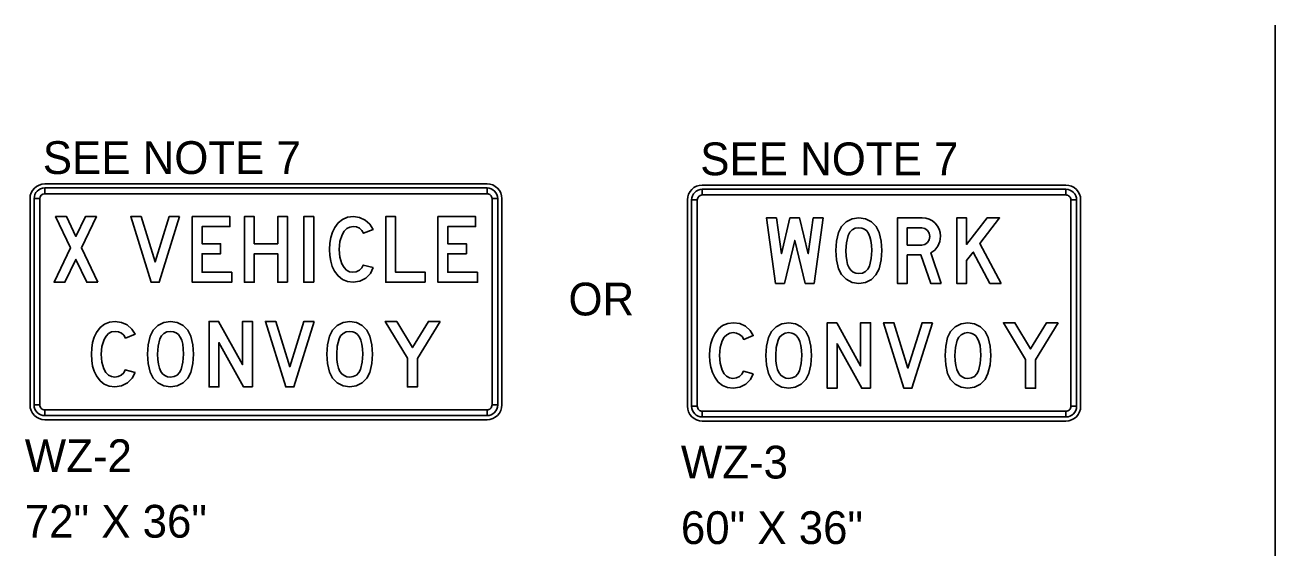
# Model space of a CAD drawing. Extents: x -747 to 834, y -5485 to -3577.
# Drawn here: x 87.7 to 316.6, y -4538 to -4442.2 of the extents above; entities that cross this region are included whole.
import ezdxf

# ---------------------------------------------------------------- set-up
doc = ezdxf.new("R2010")
doc.units = 0
doc.layers.add('Working Level 1', color=7, linetype='Continuous')

msp = doc.modelspace()

# ---------------------------------------------------------------- linework, layer by layer
at = {"layer": 'Working Level 1'}
for p, q in [((316.57, -4442.19), (316.57, -5484.51)), ((172.28, -4471.28), (91.28, -4471.28)), ((91.28, -4473.08), (91.28, -4472.03)), ((172.28, -4472.03), (172.28, -4473.08)), ((278.28, -4471.51), (211.68, -4471.51)), ((211.68, -4473.31), (211.68, -4472.26)), ((278.28, -4472.26), (278.28, -4473.31)), ((88.58, -4473.98), (88.58, -4511.77)), ((89.33, -4473.98), (90.38, -4473.98)), ((173.18, -4473.98), (174.23, -4473.98)), ((174.98, -4511.77), (174.98, -4473.98)), ((208.98, -4474.21), (208.98, -4512.01)), ((209.73, -4474.21), (210.78, -4474.21)), ((279.18, -4474.21), (280.23, -4474.21)), ((280.98, -4512.01), (280.98, -4474.21)), ((90.38, -4511.77), (89.33, -4511.77)), ((174.23, -4511.77), (173.18, -4511.77)), ((91.28, -4513.72), (91.28, -4512.67)), ((172.28, -4512.67), (172.28, -4513.72)), ((210.78, -4512.01), (209.73, -4512.01)), ((211.68, -4513.96), (211.68, -4512.91)), ((278.28, -4512.91), (278.28, -4513.96)), ((280.23, -4512.01), (279.18, -4512.01)), ((91.28, -4514.47), (172.28, -4514.47)), ((211.68, -4514.71), (278.28, -4514.71))]:
    msp.add_line(p, q, dxfattribs=at)
for points in [[(172.28, -4472.03), (91.28, -4472.03), (91.28, -4473.08), (172.28, -4473.08), (172.28, -4472.03)], [(278.28, -4472.26), (211.68, -4472.26), (211.68, -4473.31), (278.28, -4473.31), (278.28, -4472.26)], [(89.33, -4473.98), (89.33, -4511.77), (90.38, -4511.77), (90.38, -4473.98), (89.33, -4473.98)], [(174.23, -4511.77), (174.23, -4473.98), (173.18, -4473.98), (173.18, -4511.77), (174.23, -4511.77)], [(209.73, -4474.21), (209.73, -4512.01), (210.78, -4512.01), (210.78, -4474.21), (209.73, -4474.21)], [(280.23, -4512.01), (280.23, -4474.21), (279.18, -4474.21), (279.18, -4512.01), (280.23, -4512.01)], [(100.98, -4489.28), (97.99, -4482.99), (100.73, -4477.28), (98.72, -4477.28), (96.98, -4480.9), (95.26, -4477.28), (93.25, -4477.28), (95.98, -4483), (92.97, -4489.28), (94.97, -4489.28), (96.98, -4485.1), (98.97, -4489.28)], [(115.96, -4477.28), (114.07, -4477.28), (111.49, -4485.57), (108.92, -4477.28), (107.03, -4477.28), (110.75, -4489.28), (112.24, -4489.28)], [(125.53, -4487.46), (120.09, -4487.46), (120.09, -4484.07), (123.49, -4484.07), (123.49, -4482.26), (120.09, -4482.26), (120.09, -4479.09), (125.17, -4479.09), (125.17, -4477.28), (118.28, -4477.28), (118.28, -4489.28), (125.53, -4489.28)], [(135.76, -4489.28), (135.76, -4477.28), (133.95, -4477.28), (133.95, -4482.26), (129.65, -4482.26), (129.65, -4477.28), (127.84, -4477.28), (127.84, -4489.28), (129.65, -4489.28), (129.65, -4484.07), (133.95, -4484.07), (133.95, -4489.28)], [(140.53, -4489.28), (140.53, -4477.28), (138.72, -4477.28), (138.72, -4489.28)], [(151.41, -4486.61), (149.6, -4486.15), (149.33, -4486.68), (148.89, -4487.1), (148.33, -4487.37), (147.7, -4487.46), (147.07, -4487.37), (146.53, -4487.08), (146.08, -4486.6), (145.71, -4485.94), (145.34, -4484.7), (145.22, -4483.28), (145.34, -4481.84), (145.72, -4480.6), (146.1, -4479.94), (146.57, -4479.47), (147.12, -4479.18), (147.76, -4479.09), (148.36, -4479.17), (148.91, -4479.42), (149.36, -4479.81), (149.67, -4480.31), (151.41, -4479.63), (150.83, -4478.67), (149.97, -4477.92), (148.93, -4477.44), (147.79, -4477.28), (146.73, -4477.4), (145.81, -4477.78), (145.03, -4478.4), (144.37, -4479.28), (143.95, -4480.14), (143.65, -4481.1), (143.47, -4482.14), (143.41, -4483.27), (143.46, -4484.4), (143.64, -4485.44), (143.94, -4486.39), (144.36, -4487.25), (145, -4488.14), (145.78, -4488.77), (146.69, -4489.15), (147.73, -4489.28), (148.95, -4489.09), (150.05, -4488.54), (150.9, -4487.68)], [(160.97, -4489.28), (160.97, -4487.46), (155.53, -4487.46), (155.53, -4477.28), (153.72, -4477.28), (153.72, -4489.28)], [(170.53, -4487.46), (165.09, -4487.46), (165.09, -4484.07), (168.49, -4484.07), (168.49, -4482.26), (165.09, -4482.26), (165.09, -4479.09), (170.17, -4479.09), (170.17, -4477.28), (163.28, -4477.28), (163.28, -4489.28), (170.53, -4489.28)], [(233.84, -4477.51), (232.01, -4477.51), (231.09, -4484.08), (229.51, -4477.51), (227.75, -4477.51), (226.17, -4484.09), (225.25, -4477.51), (223.42, -4477.51), (225.1, -4489.51), (226.73, -4489.51), (228.63, -4481.62), (230.53, -4489.51), (232.16, -4489.51)], [(244.54, -4483.5), (244.42, -4481.79), (244.06, -4480.19), (243.52, -4479.11), (242.66, -4478.25), (241.57, -4477.7), (240.35, -4477.51), (239.13, -4477.7), (238.05, -4478.25), (237.19, -4479.11), (236.66, -4480.2), (236.29, -4481.8), (236.17, -4483.5), (236.29, -4485.2), (236.66, -4486.81), (237.19, -4487.9), (238.05, -4488.76), (239.13, -4489.32), (240.35, -4489.51), (241.57, -4489.33), (242.65, -4488.77), (243.5, -4487.92), (244.05, -4486.83), (244.42, -4485.22)], [(242.73, -4483.51), (242.63, -4484.97), (242.31, -4486.32), (242.02, -4486.89), (241.57, -4487.33), (241, -4487.61), (240.36, -4487.7), (239.8, -4487.64), (239.32, -4487.44), (238.91, -4487.11), (238.57, -4486.65), (238.31, -4486.06), (238.13, -4485.34), (238.01, -4484.49), (237.98, -4483.51), (238.08, -4482.06), (238.4, -4480.71), (238.69, -4480.14), (239.14, -4479.7), (239.71, -4479.42), (240.36, -4479.32), (240.92, -4479.39), (241.4, -4479.58), (241.8, -4479.91), (242.14, -4480.37), (242.4, -4480.96), (242.58, -4481.68), (242.69, -4482.53)], [(255.43, -4489.51), (253.53, -4483.91), (254.27, -4483.39), (254.85, -4482.66), (255.22, -4481.81), (255.34, -4480.88), (255.28, -4480.21), (255.09, -4479.59), (254.78, -4479.02), (254.34, -4478.5), (253.82, -4478.07), (253.24, -4477.76), (252.62, -4477.57), (251.95, -4477.51), (247.42, -4477.51), (247.42, -4489.51), (249.23, -4489.51), (249.23, -4484.3), (251.74, -4484.3), (253.52, -4489.51)], [(249.23, -4482.49), (249.23, -4479.32), (251.87, -4479.32), (252.44, -4479.44), (252.93, -4479.79), (253.26, -4480.3), (253.37, -4480.91), (253.26, -4481.52), (252.93, -4482.03), (252.44, -4482.38), (251.87, -4482.49)], [(266.42, -4489.51), (262.52, -4482.2), (266.13, -4477.51), (263.85, -4477.51), (260.1, -4482.37), (260.1, -4477.51), (258.29, -4477.51), (258.29, -4489.51), (260.1, -4489.51), (260.1, -4485.34), (261.31, -4483.78), (264.37, -4489.51)], [(107.82, -4505.81), (106, -4505.35), (105.74, -4505.88), (105.3, -4506.3), (104.73, -4506.57), (104.11, -4506.66), (103.48, -4506.57), (102.94, -4506.28), (102.48, -4505.8), (102.11, -4505.14), (101.74, -4503.9), (101.62, -4502.48), (101.75, -4501.04), (102.13, -4499.8), (102.51, -4499.14), (102.97, -4498.67), (103.52, -4498.38), (104.17, -4498.29), (104.77, -4498.37), (105.31, -4498.62), (105.77, -4499.01), (106.08, -4499.51), (107.82, -4498.83), (107.23, -4497.87), (106.38, -4497.12), (105.34, -4496.64), (104.2, -4496.48), (103.14, -4496.6), (102.22, -4496.98), (101.43, -4497.6), (100.78, -4498.48), (100.35, -4499.34), (100.05, -4500.3), (99.87, -4501.34), (99.81, -4502.47), (99.87, -4503.6), (100.05, -4504.64), (100.34, -4505.59), (100.77, -4506.45), (101.41, -4507.34), (102.18, -4507.97), (103.09, -4508.35), (104.14, -4508.47), (105.36, -4508.29), (106.45, -4507.74), (107.31, -4506.88)], [(118.5, -4502.47), (118.38, -4500.76), (118.01, -4499.15), (117.47, -4498.07), (116.61, -4497.21), (115.52, -4496.66), (114.3, -4496.48), (113.08, -4496.66), (112, -4497.21), (111.15, -4498.07), (110.61, -4499.16), (110.24, -4500.77), (110.12, -4502.47), (110.24, -4504.17), (110.61, -4505.78), (111.15, -4506.87), (112, -4507.73), (113.08, -4508.29), (114.3, -4508.47), (115.52, -4508.29), (116.6, -4507.74), (117.46, -4506.88), (118, -4505.8), (118.37, -4504.19)], [(129.3, -4508.47), (129.3, -4496.48), (127.49, -4496.48), (127.49, -4504.36), (123.11, -4496.48), (121.37, -4496.48), (121.37, -4508.47), (123.18, -4508.47), (123.18, -4500.33), (127.7, -4508.47)], [(140.62, -4496.48), (138.73, -4496.48), (136.15, -4504.77), (133.58, -4496.48), (131.69, -4496.48), (135.4, -4508.47), (136.89, -4508.47)], [(151.31, -4502.47), (151.19, -4500.76), (150.82, -4499.15), (150.28, -4498.07), (149.42, -4497.21), (148.34, -4496.66), (147.12, -4496.48), (145.9, -4496.66), (144.82, -4497.21), (143.96, -4498.07), (143.42, -4499.16), (143.06, -4500.77), (142.94, -4502.47), (143.06, -4504.17), (143.42, -4505.78), (143.96, -4506.87), (144.82, -4507.73), (145.9, -4508.29), (147.12, -4508.47), (148.33, -4508.29), (149.42, -4507.74), (150.27, -4506.88), (150.81, -4505.8), (151.18, -4504.19)], [(163.68, -4496.48), (161.55, -4496.48), (158.61, -4501.27), (155.73, -4496.48), (153.62, -4496.48), (157.7, -4503.22), (157.7, -4508.47), (159.51, -4508.47), (159.51, -4503.27)], [(221.02, -4506.05), (219.21, -4505.59), (218.94, -4506.11), (218.5, -4506.53), (217.94, -4506.81), (217.31, -4506.9), (216.68, -4506.8), (216.14, -4506.52), (215.68, -4506.04), (215.31, -4505.37), (214.94, -4504.14), (214.82, -4502.71), (214.95, -4501.27), (215.33, -4500.04), (215.71, -4499.38), (216.17, -4498.9), (216.73, -4498.62), (217.37, -4498.52), (217.97, -4498.61), (218.52, -4498.85), (218.97, -4499.25), (219.28, -4499.75), (221.02, -4499.07), (220.43, -4498.1), (219.58, -4497.35), (218.54, -4496.87), (217.4, -4496.71), (216.34, -4496.84), (215.42, -4497.21), (214.63, -4497.84), (213.98, -4498.71), (213.55, -4499.58), (213.25, -4500.53), (213.07, -4501.57), (213.01, -4502.7), (213.07, -4503.83), (213.25, -4504.87), (213.55, -4505.82), (213.97, -4506.69), (214.61, -4507.57), (215.39, -4508.2), (216.29, -4508.59), (217.34, -4508.71), (218.56, -4508.53), (219.65, -4507.97), (220.51, -4507.12)], [(231.7, -4502.7), (231.58, -4500.99), (231.21, -4499.39), (230.67, -4498.31), (229.81, -4497.45), (228.73, -4496.9), (227.51, -4496.71), (226.28, -4496.9), (225.21, -4497.45), (224.35, -4498.31), (223.81, -4499.4), (223.44, -4501), (223.32, -4502.7), (223.44, -4504.4), (223.81, -4506.01), (224.35, -4507.1), (225.21, -4507.96), (226.28, -4508.52), (227.51, -4508.71), (228.72, -4508.53), (229.8, -4507.97), (230.66, -4507.12), (231.2, -4506.03), (231.57, -4504.42)], [(242.5, -4508.71), (242.5, -4496.71), (240.69, -4496.71), (240.69, -4504.6), (236.31, -4496.71), (234.57, -4496.71), (234.57, -4508.71), (236.38, -4508.71), (236.38, -4500.57), (240.9, -4508.71)], [(253.82, -4496.71), (251.93, -4496.71), (249.35, -4505), (246.78, -4496.71), (244.89, -4496.71), (248.6, -4508.71), (250.09, -4508.71)], [(264.51, -4502.7), (264.39, -4500.99), (264.02, -4499.39), (263.48, -4498.31), (262.62, -4497.45), (261.54, -4496.9), (260.32, -4496.71), (259.1, -4496.9), (258.02, -4497.45), (257.16, -4498.31), (256.62, -4499.4), (256.26, -4501), (256.14, -4502.7), (256.26, -4504.4), (256.62, -4506.01), (257.16, -4507.1), (258.02, -4507.96), (259.1, -4508.52), (260.32, -4508.71), (261.53, -4508.53), (262.62, -4507.97), (263.47, -4507.12), (264.01, -4506.03), (264.38, -4504.42)], [(276.88, -4496.71), (274.75, -4496.71), (271.81, -4501.5), (268.93, -4496.71), (266.82, -4496.71), (270.9, -4503.45), (270.9, -4508.71), (272.71, -4508.71), (272.71, -4503.5)], [(116.69, -4502.48), (116.58, -4503.93), (116.26, -4505.29), (115.97, -4505.85), (115.52, -4506.29), (114.96, -4506.57), (114.32, -4506.66), (113.76, -4506.6), (113.27, -4506.4), (112.86, -4506.08), (112.53, -4505.62), (112.27, -4505.03), (112.08, -4504.31), (111.97, -4503.46), (111.93, -4502.48), (112.04, -4501.02), (112.36, -4499.67), (112.64, -4499.11), (113.09, -4498.66), (113.66, -4498.38), (114.32, -4498.29), (114.87, -4498.35), (115.35, -4498.55), (115.76, -4498.88), (116.09, -4499.33), (116.35, -4499.92), (116.54, -4500.64), (116.65, -4501.5)], [(149.5, -4502.48), (149.39, -4503.93), (149.08, -4505.29), (148.79, -4505.85), (148.34, -4506.29), (147.77, -4506.57), (147.13, -4506.66), (146.57, -4506.6), (146.08, -4506.4), (145.67, -4506.08), (145.34, -4505.62), (145.08, -4505.03), (144.89, -4504.31), (144.78, -4503.46), (144.75, -4502.48), (144.85, -4501.02), (145.17, -4499.67), (145.46, -4499.11), (145.91, -4498.66), (146.48, -4498.38), (147.13, -4498.29), (147.68, -4498.35), (148.16, -4498.55), (148.57, -4498.88), (148.91, -4499.33), (149.16, -4499.92), (149.35, -4500.64), (149.46, -4501.5)], [(229.89, -4502.71), (229.78, -4504.17), (229.47, -4505.52), (229.17, -4506.09), (228.73, -4506.53), (228.16, -4506.81), (227.52, -4506.9), (226.96, -4506.83), (226.47, -4506.64), (226.06, -4506.31), (225.73, -4505.85), (225.47, -4505.26), (225.28, -4504.54), (225.17, -4503.69), (225.14, -4502.71), (225.24, -4501.26), (225.56, -4499.91), (225.85, -4499.34), (226.3, -4498.9), (226.87, -4498.62), (227.52, -4498.52), (228.07, -4498.59), (228.55, -4498.78), (228.96, -4499.11), (229.3, -4499.57), (229.55, -4500.16), (229.74, -4500.88), (229.85, -4501.73)], [(262.7, -4502.71), (262.59, -4504.17), (262.28, -4505.52), (261.99, -4506.09), (261.54, -4506.53), (260.97, -4506.81), (260.33, -4506.9), (259.77, -4506.83), (259.28, -4506.64), (258.87, -4506.31), (258.54, -4505.85), (258.28, -4505.26), (258.09, -4504.54), (257.98, -4503.69), (257.95, -4502.71), (258.05, -4501.26), (258.37, -4499.91), (258.66, -4499.34), (259.11, -4498.9), (259.68, -4498.62), (260.33, -4498.52), (260.88, -4498.59), (261.36, -4498.78), (261.77, -4499.11), (262.11, -4499.57), (262.36, -4500.16), (262.55, -4500.88), (262.66, -4501.73)], [(91.28, -4513.72), (172.28, -4513.72), (172.28, -4512.67), (91.28, -4512.67), (91.28, -4513.72)], [(211.68, -4513.96), (278.28, -4513.96), (278.28, -4512.91), (211.68, -4512.91), (211.68, -4513.96)]]:
    msp.add_lwpolyline(points, close=True, dxfattribs=at)
for centre, radius, start, end in [((91.28, -4473.98), 2.7, 90.0002, 179.9998), ((91.28, -4473.98), 1.95, 90.0002, 179.9998), ((172.28, -4473.98), 2.7, 0, 90.0002), ((172.28, -4473.98), 1.95, 0, 90.0002), ((211.68, -4474.21), 2.7, 90.0002, 179.9998), ((211.68, -4474.21), 1.95, 90.0002, 179.9998), ((278.28, -4474.21), 2.7, 0, 90.0002), ((278.28, -4474.21), 1.95, 0, 90.0002), ((91.28, -4473.98), 0.9, 90.0002, 179.9998), ((172.28, -4473.98), 0.9, 0, 90.0002), ((211.68, -4474.21), 0.9, 90.0002, 179.9998), ((278.28, -4474.21), 0.9, 0, 90.0002), ((91.28, -4511.77), 2.7, 179.9998, 270.0001), ((91.28, -4511.77), 1.95, 179.9998, 270.0001), ((91.28, -4511.77), 0.9, 179.9998, 270.0001), ((172.28, -4511.77), 2.7, 270.0001, 0.0003), ((172.28, -4511.77), 1.95, 270.0001, 0.0003), ((172.28, -4511.77), 0.9, 270.0001, 0.0003), ((211.68, -4512.01), 2.7, 179.9998, 270.0001), ((211.68, -4512.01), 1.95, 179.9998, 270.0001), ((211.68, -4512.01), 0.9, 179.9998, 270.0001), ((278.28, -4512.01), 2.7, 270.0001, 0.0003), ((278.28, -4512.01), 1.95, 270.0001, 0.0003), ((278.28, -4512.01), 0.9, 270.0001, 0.0003)]:
    msp.add_arc(centre, radius, start, end, dxfattribs=at)

# ---------------------------------------------------------------- texts
for p in [(90.92, -4469.47), (211.32, -4469.7)]:
    msp.add_text('SEE NOTE 7 ', height=6, dxfattribs=at).set_placement(p)
for s, p in [('OR', (187.18, -4495.37)), ('WZ-2', (87.62, -4524.06)), ('WZ-3', (207.77, -4525.23)), ('72" X 36"', (87.62, -4536.06)), ('60" X 36"', (207.77, -4537.23))]:
    msp.add_text(s, height=6, rotation=0, dxfattribs=at).set_placement(p)

doc.saveas('drawing.dxf')
